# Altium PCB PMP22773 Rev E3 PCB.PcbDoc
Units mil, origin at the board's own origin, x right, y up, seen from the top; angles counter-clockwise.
Board outline 1255 x 1328.74 mil, 4 copper layers (Top Layer, GND, Signal, Bottom Layer), stack 70.356 mil thick; 34 components, 28 nets, 106 pads, 30 vias.
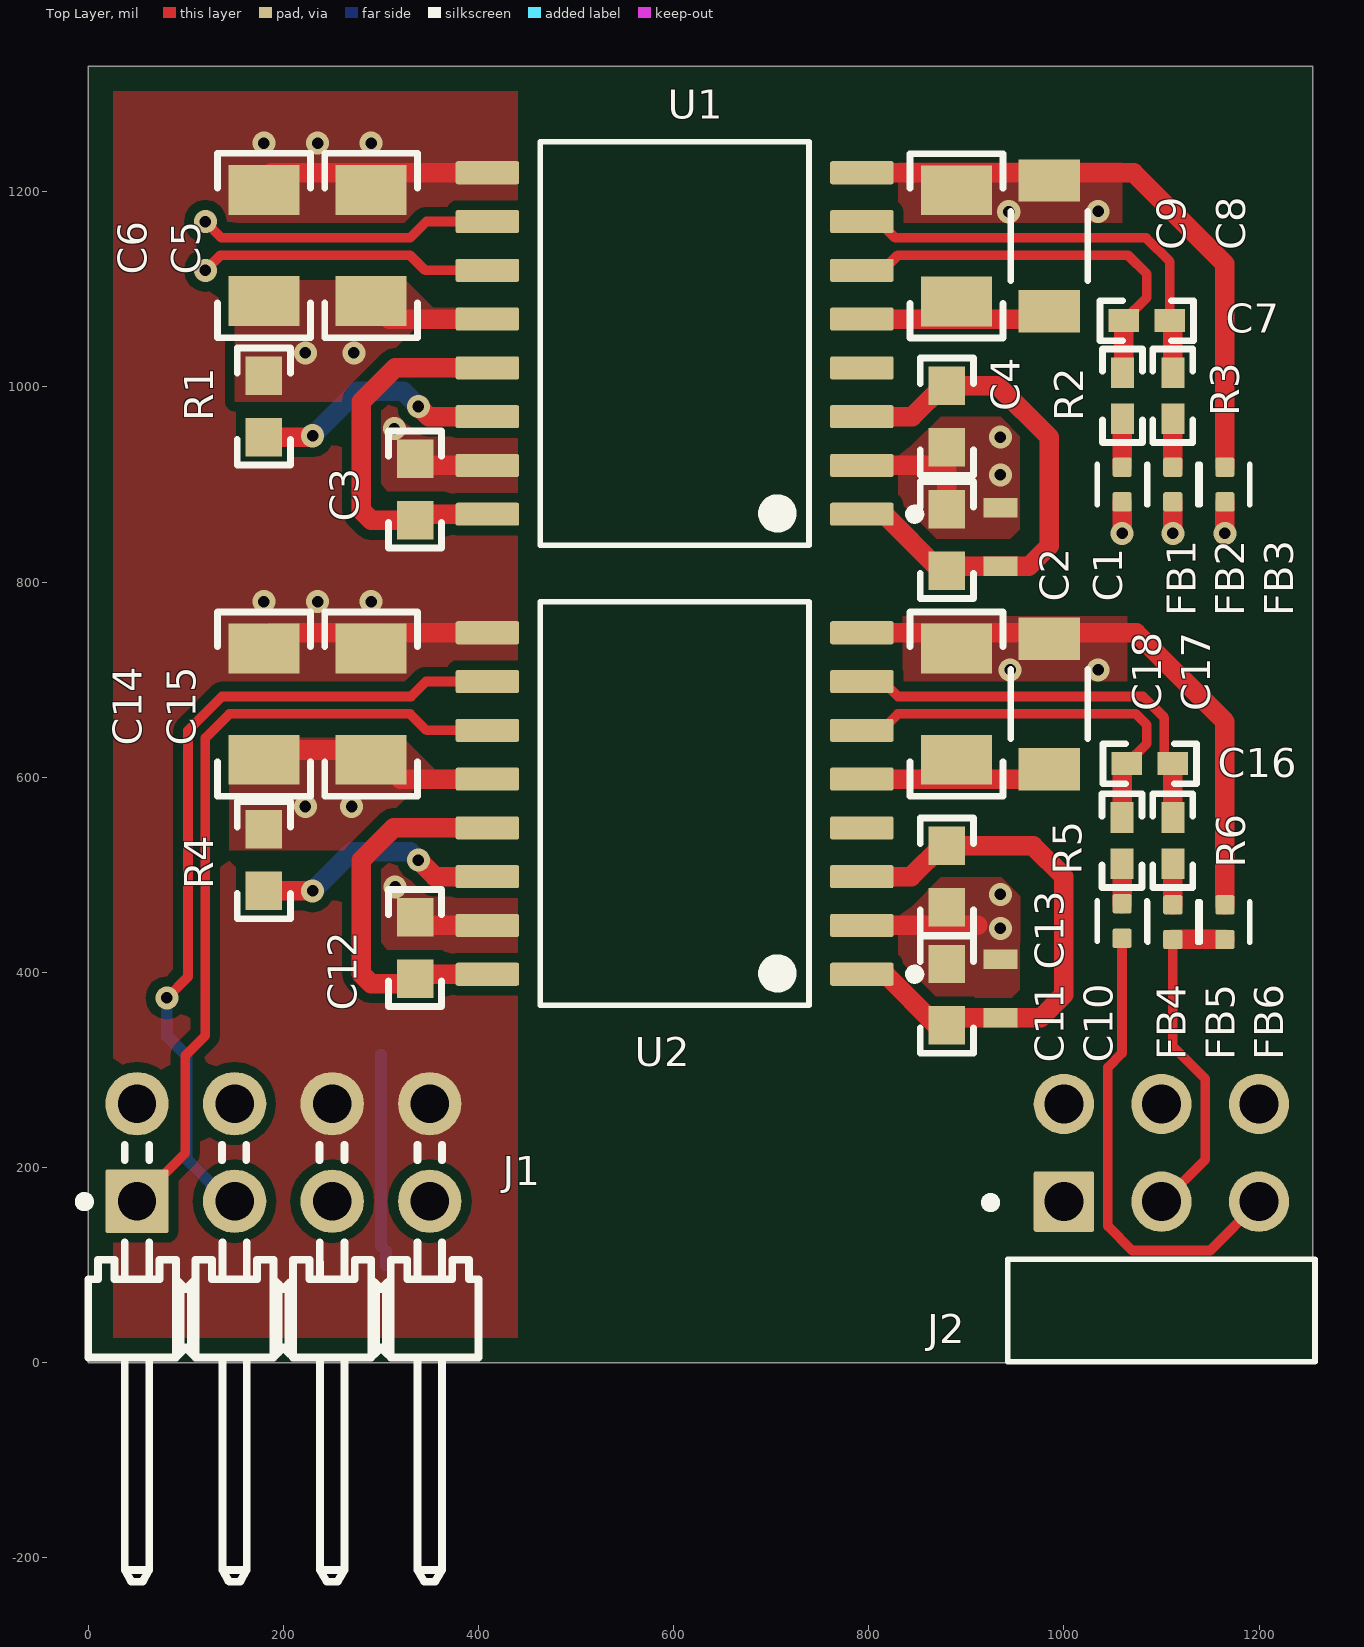
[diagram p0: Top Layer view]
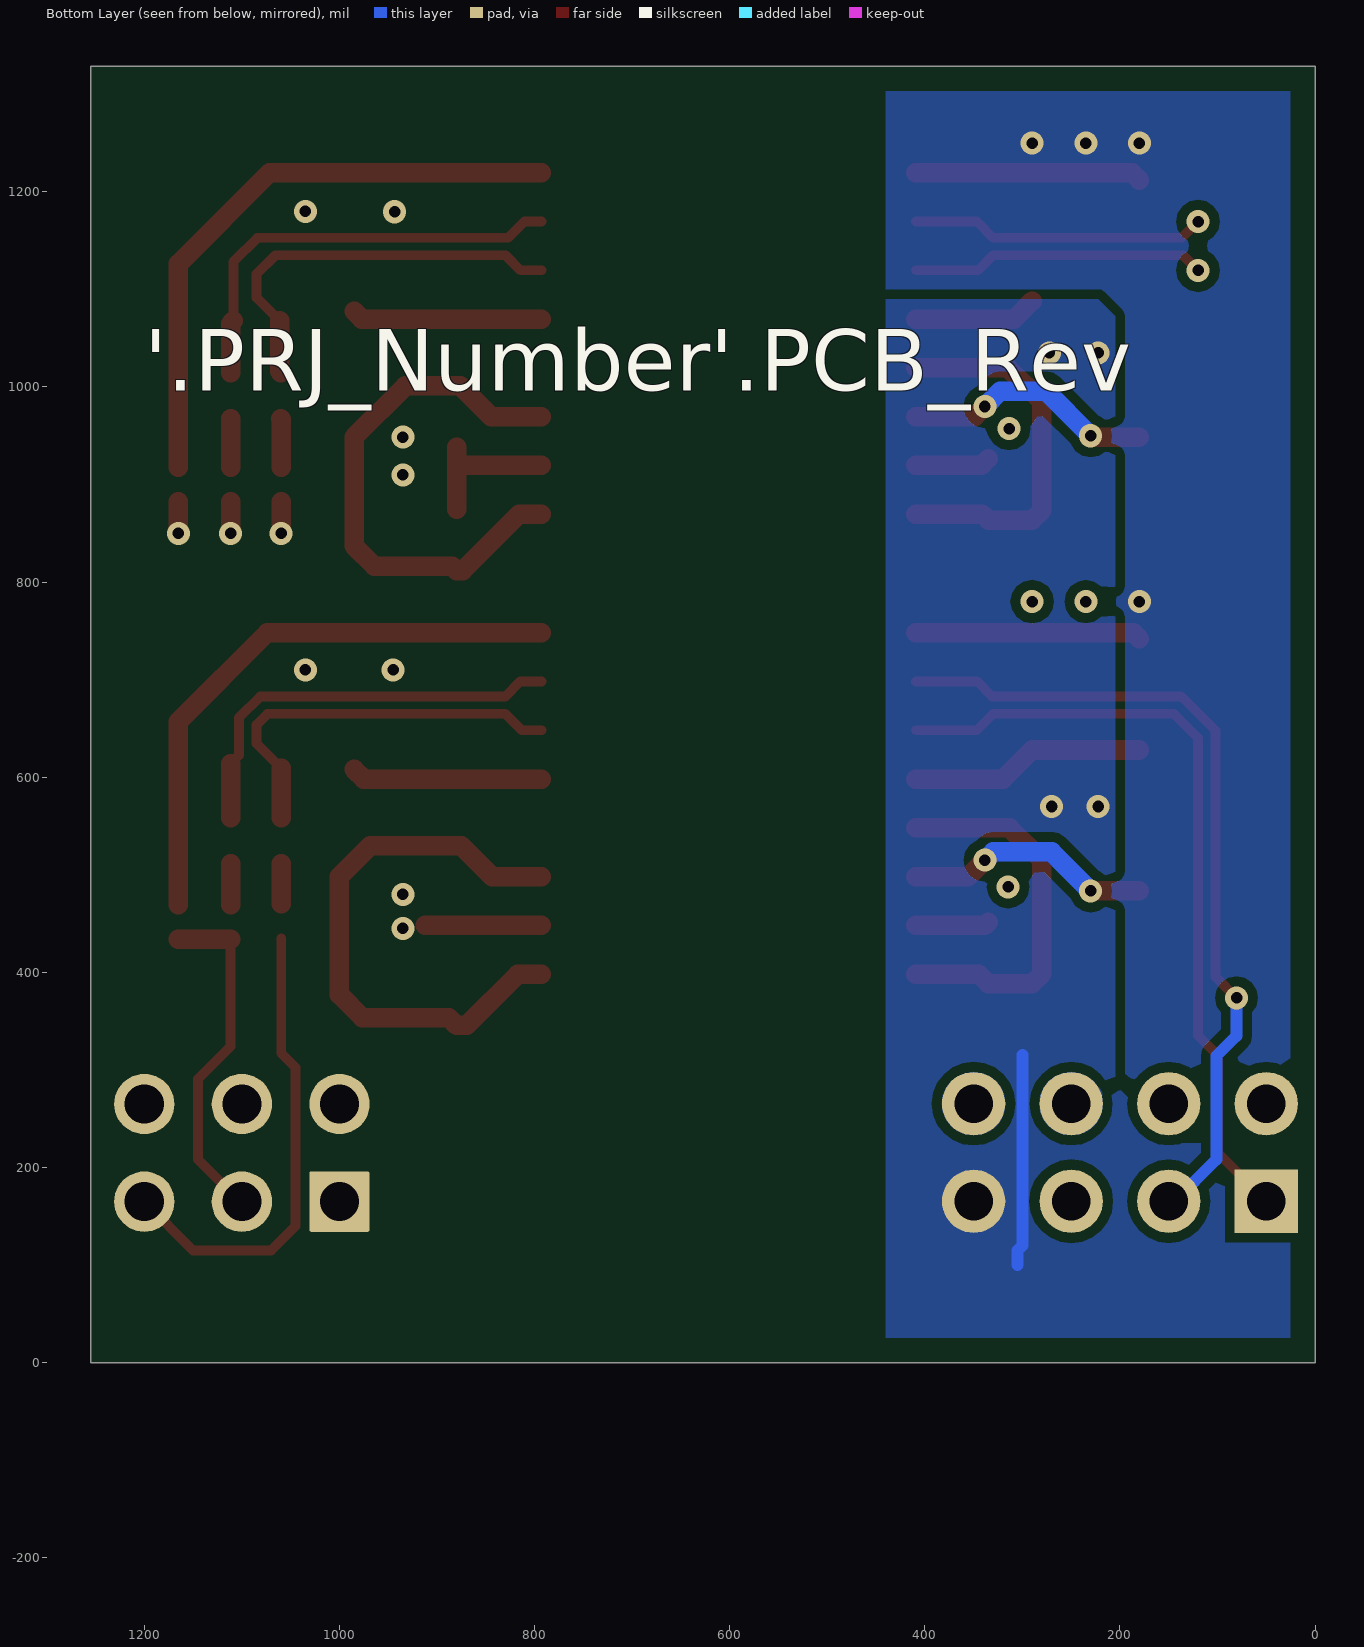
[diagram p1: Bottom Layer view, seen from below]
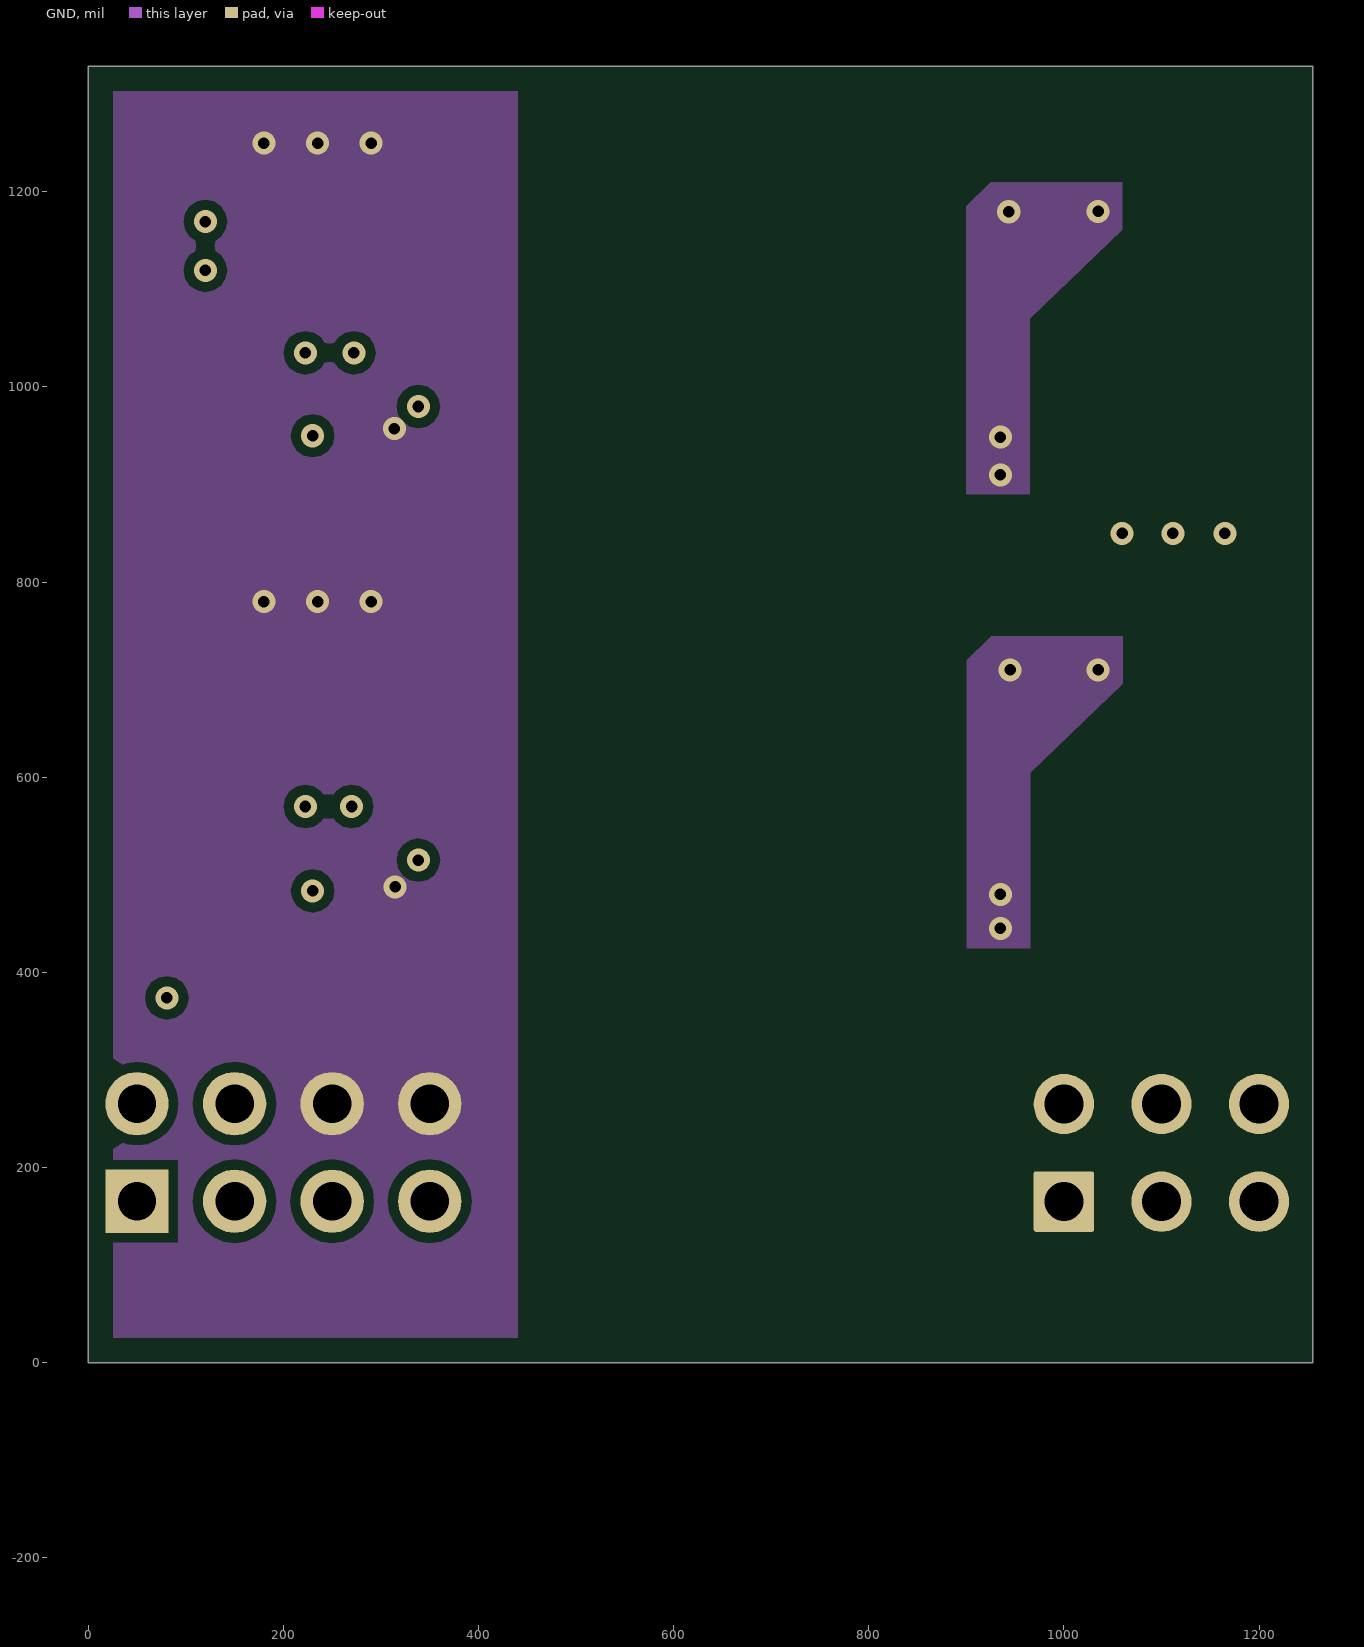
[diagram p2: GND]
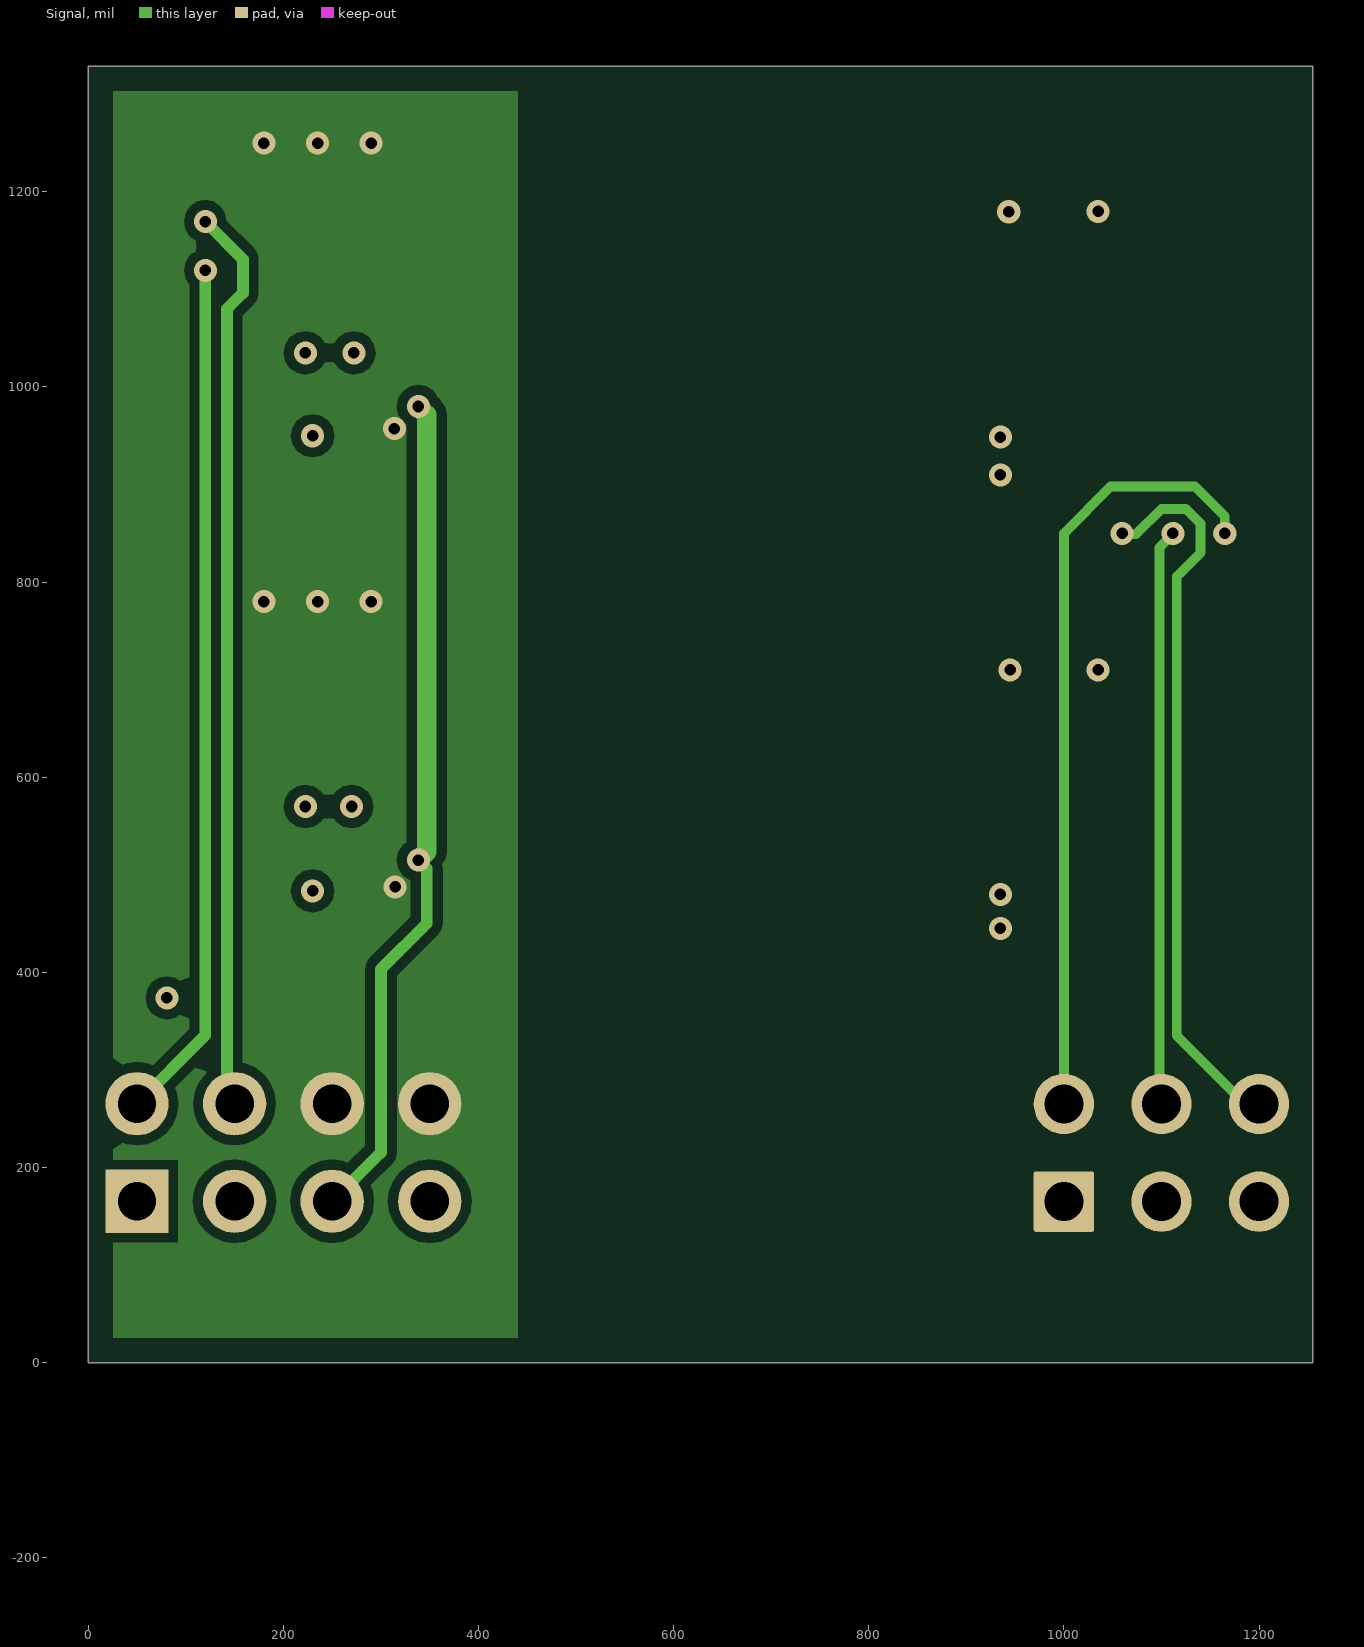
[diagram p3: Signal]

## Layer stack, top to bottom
Top Solder: solder mask 0.4, Solder Resist, Dk 3.5
Top Layer: signal copper 1.4
Dielectric 1: prepreg 2.8, PP-006, Dk 4.1
GND: signal copper 1.378
Dielectric1: core 59.2, FR-4, Dk 4.8
Signal: signal copper 1.378
Dielectric 2: prepreg 2.8, PP-006, Dk 4.1
Bottom Layer: signal copper 1.4
Bottom Solder: solder mask 0.4, Solder Resist, Dk 3.5

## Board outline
0,0 1255,0 1255,1328.74 0,1328.74

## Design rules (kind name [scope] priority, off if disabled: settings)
AcuteAngle [All] p1: minimum=4.50000000000000E+0001 checktracksonly=FALSE
AssemblyTestPointUsage [All] p1: valid=2
BoardOutlineClearance BoardOutlineClearance_MountingHoles [OnCopper and InComponentClass('Mounting Holes')] p1: gap=39.37 ignorepadtopadclearanceinfootprint=FALSE
BoardOutlineClearance BoardOutlineClearance_Poly [OnCopper and IsPoly] p2: gap=25 ignorepadtopadclearanceinfootprint=FALSE
BoardOutlineClearance [OnCopper and Not InComponentClass('Logo') and not InComponentClass('FiducialMark') and not InRegion(1000,500,4000,800) and not InPoly] p3: gap=75 ignorepadtopadclearanceinfootprint=FALSE
Clearance Clearance_Keepouts [((IsTrack Or IsArc) And Not InPoly) And IsFree and IsKeepOut vs ((IsTrack Or IsArc) And Not InPoly) And IsFree and IsKeepOut] p1: gap=0 ignorepadtopadclearanceinfootprint=FALSE
Clearance Clearance_Poly [InPolygon] p2: gap=10 ignorepadtopadclearanceinfootprint=TRUE
Clearance Clearance_FiducialMark [IsKeepOut and InComponentClass('FiducialMark') vs IsPad and InComponentClass('FiducialMark')] p3: gap=0 ignorepadtopadclearanceinfootprint=FALSE
Clearance [All] p4: gap=7.87 ignorepadtopadclearanceinfootprint=TRUE
ComponentClearance ComponentClearance_MountingHoles_FiducialMarks [InComponentClass('Mounting Holes') vs InComponentClass('FiducialMark')] p1: gap=50 collisioncheckmode=3 verticalgap=10 showdistances=FALSE
ComponentClearance ComponentClearance_Shunt [InComponentClass('Header') vs InComponentClass('Shunt')] p2: gap=0 collisioncheckmode=3 verticalgap=0 showdistances=FALSE
ComponentClearance ComponentClearance_Logo [InComponentClass('Logo')] p3: gap=50 collisioncheckmode=3 verticalgap=10 showdistances=FALSE
ComponentClearance ComponentClearance_ScrewToNut [(HasFootprint('NY PMS 440 0025 PH')) vs (HasFootprint('Keystone_1902C'))] p4: gap=5 collisioncheckmode=3 verticalgap=10 showdistances=FALSE
ComponentClearance ComponentClearance_MountingHoles [InComponentClass('Mounting Holes')] p5: gap=250 collisioncheckmode=3 verticalgap=100000 showdistances=FALSE
ComponentClearance ComponentClearance_SmallPassives [HasFootprint('0201*') or HasFootprint('0402*') or HasFootprint('0508') or HasFootprint('0603*') or HasFootprint('0612') or HasFootprint('0805*') or HasFootprint('0815*') or HasFootprint('0830*') or HasFootprint('1206*') or HasFootprint('1210*') or HasFootprint('1808*') or HasFootprint('1812*') or HasFootprint('1825*') or HasFootprint('2010*') or HasFootprint('2220*') or HasFootprint('2225*') or HasFootprint('2512*') or HasFootprint('2728*') or HasFootprint('3518*') vs HasFootprint('0201*') or HasFootprint('0402*') or HasFootprint('0508') or HasFootprint('0603*') or HasFootprint('0612') or HasFootprint('0805*') or HasFootprint('0815*') or HasFootprint('0830*') or HasFootprint('1206*') or HasFootprint('1210*') or HasFootprint('1808*') or HasFootprint('1812*') or HasFootprint('1825*') or HasFootprint('2010*') or HasFootprint('2220*') or HasFootprint('2225*') or HasFootprint('2512*') or HasFootprint('2728*') or HasFootprint('3518*')] p6: gap=14.96 collisioncheckmode=3 verticalgap=10 showdistances=FALSE
ComponentClearance ComponentClearance_THtoSMT [IsThruComponent vs IsSMTComponent] p7: gap=40 collisioncheckmode=3 verticalgap=30 showdistances=FALSE
ComponentClearance ComponentClearance_THtoTH [IsThruComponent vs IsThruComponent] p8: gap=30 collisioncheckmode=3 verticalgap=30 showdistances=FALSE
ComponentClearance [All] p9: gap=30 collisioncheckmode=3 verticalgap=10 showdistances=FALSE
DiffPairsRouting [All] p1: maxlimit=100 minlimit=10 mostfreqgap=10 toplayer_minwidth=15 toplayer_maxwidth=15 toplayer_prefwidth=15 midlayer1_minwidth=15 midlayer1_maxwidth=15 midlayer1_prefwidth=15 midlayer2_minwidth=15 midlayer2_maxwidth=15 midlayer2_prefwidth=15 bottomlayer_minwidth=15 bottomlayer_maxwidth=15 bottomlayer_prefwidth=15 maxuncoupledlength=1000
FabricationTestPointUsage TestPointUsage [All] p1: valid=2 allowmultiple=FALSE
FabricationTestpoint Testpoint [All] p1: side=3 testpointundercomponent=TRUE minsize=40 maxsize=100 preferedsize=60 minholesize=0 maxholesize=40 preferedholesize=32 testpointgrid=1 allowsidetop=TRUE allowsidebottom=TRUE usegrid=TRUE gridtolerance=0.01
FanoutControl Fanout_LCC [IsLCC] p1: bgadir=Out bgaviamode=Centered fanoutstyle=Auto fanoutdirection=Alternating viagrid=1 // Fanout_LCC (Default Rule)
FanoutControl Fanout_BGA [IsBGA] p2: bgadir=Out bgaviamode=Centered fanoutstyle=Auto fanoutdirection=Alternating viagrid=1 // Fanout_BGA (Default Rule)
FanoutControl Fanout_Default [All] p4: bgadir=Out bgaviamode=Centered fanoutstyle=Auto fanoutdirection=Alternating viagrid=1 // Fanout_Default (Default Rule)
FanoutControl Fanout_Small [(CompPinCount < 5)] p5: bgadir=Out bgaviamode=Centered fanoutstyle=Auto fanoutdirection=OutThenIn viagrid=1 // Fanout_Small (Default Rule)
HoleSize [All] p1: absolutevalues=TRUE maxlimit=251 minlimit=7.87 maxpercent=80.000 minpercent=20.000
MinimumAnnularRing MinimumAnnularRing_ThermalPadVias [IsVia and InAnyComponent] p1: minimumring=5.91
MinimumAnnularRing [All] p2: minimumring=7.87
MinimumSolderMaskSliver MinimumSolderMaskSliver_Logo [InComponentClass('Logo') vs InComponentClass('Logo')] p1: minsoldermaskwidth=0.7
MinimumSolderMaskSliver [All] p2: minsoldermaskwidth=3.94
PlaneConnect [All] p1: planeconnectstyle=Relief reliefexpansion=10 reliefentries=4 reliefconductorwidth=10 reliefairgap=10
PolygonConnect [All] p1: connectstyle=Direct reliefconductorwidth=10 reliefentries=4 polygonreliefangle="90 Angle" airgapwidth=10
RoutingVias ThermalPadVias [IsVia and InAnyComponent] p1: holewidth=7.87 width=19.68 viastyle="Through Hole" minholewidth=7.87 minwidth=19.68 maxholewidth=12.99 maxwidth=23.62
RoutingVias [All] p2: holewidth=16 width=34 viastyle="Through Hole" minholewidth=7.87 minwidth=26 maxholewidth=40 maxwidth=65
SilkToBoardRegionClearance [Not ((IsComment or IsDesignator) And (Hide <> 'False')) and not InRegion(1000,500,4000,800)] p1:
SilkToSilkClearance SilkToSilkClearance_Pb-FreeLogo [(HasFootprint('Pb-Free_Overlay_Medium') OR HasFootprint('Pb-Free_Overlay_Small')) vs (HasFootprint('Pb-Free_Overlay_Medium') OR HasFootprint('Pb-Free_Overlay_Small'))] p1: silktosilkclearance=0
SilkToSilkClearance [All] p2: silktosilkclearance=3.94
SilkToSolderMaskClearance SilkToComponentPadClearance [(IsPad or IsFill or IsRegion) and InAnycomponent] p1: minsilkscreentomaskgap=5 clearancetoexposedcopper=TRUE
SilkToSolderMaskClearance "Silk to Solder Mask Opening" [All] p2: minsilkscreentomaskgap=3.94 clearancetoexposedcopper=FALSE
SolderMaskExpansion [All] p1: expansion=1.97 istentingtop=FALSE
UnRoutedNet [All] p1: checkbadconnections=TRUE
Width [All] p1: maxlimit=100 minlimit=6 preferedwidth=10 checkconnectedcopper=TRUE
14 further rules are at their usual default settings.

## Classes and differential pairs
component class Header: J1

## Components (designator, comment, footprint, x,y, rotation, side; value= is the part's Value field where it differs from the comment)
C1 "CGA3E1X7R1E105K080AC" 0603S 935,846.22 r90 top value=1uF
C2 "C0603C102K5RACTU" 0603 880,843.11 r90 top value=1000pF
C3 "C0603C104K5RACAUTO" 0603 335,895 r90 top value=0.1uF
C4 "C0603C104K5RACAUTO" 0603 880,969.58 r90 top value=0.1uF
C5 "12065C102KAT2A" 1206 290,1145 r90 top value=1000pF
C6 "12063C105KAT2A" 1206 180,1145 r90 top value=1uF
C7 "CGA2B3X7R1H104K050BB" 0402 1085,1067.91 r180 top value=0.1uF
C8 "C3216NP01H104J160AA" 1206_190 985,1144.58 r90 top value=0.1uF
C9 "12065C102KAT2A" 1206 890,1144.58 r90 top value=1000pF
C10 "CGA3E1X7R1E105K080AC" 0603S 935,383.5 r90 top value=1uF
C11 "C0603C102K5RACTU" 0603 880,377.12 r90 top value=1000pF
C12 "C0603C104K5RACAUTO" 0603 335,425 r90 top value=0.1uF
C13 "C0603C104K5RACAUTO" 0603 880,498.09 r90 top value=0.1uF
C14 "12065C102KAT2A" 1206 180,675 r90 top value=1000pF
C15 "12063C105KAT2A" 1206 290,675 r90 top value=1uF
C16 "CGA2B2X7R1H102K050BA" 0402 1088.03,613.86 r180 top value=1000pF
C17 "C3216NP01H104J160AA" 1206_190 985,675 r90 top value=0.1uF
C18 "12065C102KAT2A" 1206 890,675 r90 top value=1000pF
FB1 "MMZ1005Y182CTD25" FP-MMZ1005Y182CTD25_0402-MFG 1059.69,900 r90 top
FB2 "MMZ1005Y182CTD25" FP-MMZ1005Y182CTD25_0402-MFG 1111.65,900 r90 top
FB3 "MMZ1005Y182CTD25" FP-MMZ1005Y182CTD25_0402-MFG 1165,900 r90 top
FB4 "MMZ1005Y182CTD25" FP-MMZ1005Y182CTD25_0402-MFG 1059.69,452.6 r90 top
FB5 "MMZ1005Y182CTD25" FP-MMZ1005Y182CTD25_0402-MFG 1111.65,451.5 r90 top
FB6 "MMZ1005Y182CTD25" FP-MMZ1005Y182CTD25_0402-MFG 1165,451.5 r90 top
J1 "TSW-104-09-G-D-RA" Samtec_TSW-104-09-G-D-RA 200,215.39 r0 top
J2 "TSW-103-08-G-D-RA" FP-TSW-103-08-G-D-RA_HDR6-MFG 1100,55.94 r0 top
R1 "CRCW060347K0JNEA" 0603 180,980 r270 top value=47k
R2 "CRCW040239R2FKED" 0402 1060,991.08 r90 top value=39.2
R3 "CRCW040239R2FKED" 0402 1111.65,991.08 r90 top value=39.2
R4 "CRCW060347K0JNEA" 0603 180,515 r270 top value=47k
R5 "CRCW04020000Z0ED" 0402 1059.69,535 r90 top value=0
R6 "CRCW04020000Z0ED" 0402 1111.65,535 r90 top value=0
U1 "PAMC3302DWER" DWE0016A-MFG 601,1044.58 r180 top
U2 "AMC3330QDWERQ1" DWE0016A-MFG 601,573.09 r180 top

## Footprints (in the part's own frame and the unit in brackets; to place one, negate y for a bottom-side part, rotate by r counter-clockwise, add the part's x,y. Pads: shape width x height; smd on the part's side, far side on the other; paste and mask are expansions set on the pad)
0402 [mm] "0402 from SM-752 data"
  rect 0.8x0.6 smd: 1(-0.6,0) 2(0.6,0)
  silkscreen extent -1.22,-0.52 1.22,0.52, body extent -0.55,-0.3 0.55,0.3, height 0.6
0603 [mm] "0603 from SM-752 data"
  rect 1x0.95 smd: 1(-0.8,0) 2(0.8,0)
  silkscreen extent -1.52,-0.69 1.52,0.69, body extent -0.87,-0.47 0.87,0.47, height 1
0603S [mil]
  rect 20x35 smd: 1(-30,0) 2(30,0)
  body extent -34,-19 34,19, height 39
1206 [mm] "1206 from SM-752 data"
  rect 1.3x1.85 smd: 1(-1.45,0) 2(1.45,0)
  silkscreen extent -2.4,-1.21 2.4,1.21, body extent -1.7,-0.9 1.7,0.9, height 1.35
1206_190 [mm] "1206_190"
  rect 1.1x1.6 smd: 1(-1.7,0) 2(1.7,0)
  silkscreen extent -0.9,-1 0.9,1, body extent -1.75,-0.95 1.75,0.95, height 1.9
DWE0016A-MFG [mm]
  rrect17% 1.65x0.6 smd paste+0 mask+0: 1(-4.875,4.445) 2(-4.875,3.175) 3(-4.875,1.905) 4(-4.875,0.635) 5(-4.875,-0.635) 6(-4.875,-1.905) 7(-4.875,-3.175) 8(-4.875,-4.445) 9(4.875,-4.445) 10(4.875,-3.175) 11(4.875,-1.905) 12(4.875,-0.635) 13(4.875,0.635) 14(4.875,1.905) 15(4.875,3.175) 16(4.875,4.445)
  silkscreen extent -6.38,-5.25 3.5,5.25, body extent -5.8,-5.5 5.8,5.5, height 0.25
FP-MMZ1005Y182CTD25_0402-MFG [mm]
  rrect20% 0.5x0.5 smd paste+0 mask+0: 1(-0.45,0) 2(0.45,0)
  silkscreen extent -0.53,-0.65 0.53,0.65, body extent -0.8,-0.38 0.8,0.38, height 0.25
FP-TSW-103-08-G-D-RA_HDR6-MFG [mm]
  rrect6% 1.57x1.57 hole 1.02 paste-1000 mask+0: 1(-2.54,2.77)
  round 1.57 hole 1.02 paste-1000 mask+0: 2(-2.54,5.31) 3(0,2.77) 4(0,5.31) 5(2.54,2.77) 6(2.54,5.31)
  silkscreen extent -4.57,-1.4 4,2.87, body extent -4.1,-7.54 4.1,6.19, height 0.25
Samtec_TSW-104-09-G-D-RA [mm] "Samtec Right Angle Header"
  rrect6% 1.65x1.65 / inner rect 1.65x1.65 / far side rect 1.65x1.65 hole 1: 1(-3.81,-1.27)
  round 1.65 hole 1: 2(-3.81,1.27) 3(-1.27,-1.27) 4(-1.27,1.27) 5(1.27,-1.27) 6(1.27,1.27) 7(3.81,-1.27) 8(3.81,1.27)
  silkscreen extent -5.3,-11.18 5.08,0.2, body extent -5.08,-11.18 5.08,1.59, height 5.51

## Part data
C1 C10: library part CMP-0076705-3, "CAP, CERM, 1 µF, 25 V,+/- 10%, X7R, AEC-Q200 Grade 1, 0603", Cap_Case=1.6x0.8x0.8mm, Manufacturer=TDK, Supplier Part Number 1=445-6931-1-ND, TempCo=X7R, Tolerance_%=10%, Value2=25V, ValueDisplayed=1µF
C2 C11: library part CMP-0006847-4, "CAP, CERM, 1000 pF, 50 V, +/- 10%, X7R, 0603", Cap_Case=0603, Manufacturer=Kemet, Supplier Part Number 1=399-1082-1-ND, TempCo=X7R, Tolerance_%=10%, Value1=Unknown, Value2=50V, ValueDisplayed=1000pF
C3 C4 C12 C13: library part CMP-0079602-1, "CAP, CERM, 0.1 µF, 50 V,+/- 10%, X7R, AEC-Q200 Grade 1, 0603", Cap_Case=0603, Manufacturer=Kemet, Supplier Part Number 1=399-6856-1-ND, TempCo=X7R, Tolerance_%=10%, Value2=50V, ValueDisplayed=0.1µF
C5 C9 C14 C18: library part CMP-0008530-2, "CAP, CERM, 1000 pF, 50 V, +/- 10%, X7R, 1206", Cap_Case=1206, Manufacturer=AVX, Supplier Part Number 1=478-1530-1-ND, TempCo=X7R, Tolerance_%=10%, Value1="0.427 ohm", Value2=50V, ValueDisplayed=1000pF
C6 C15: library part CMP-0008509-2, "CAP, CERM, 1 uF, 25 V, +/- 10%, X7R, 1206", Cap_Case=1206, Manufacturer=AVX, Supplier Part Number 1=478-1567-1-ND, TempCo=X7R, Tolerance_%=10%, Value1="0.013 ohm", Value2=25V, ValueDisplayed=1uF
C7: library part CMP-0006325-2, "CAP, CERM, 0.1 uF, 50 V, +/- 10%, X7R, AEC-Q200 Grade 1, 0402", Cap_Case=0402, Manufacturer=TDK, Supplier Part Number 1=445-6899-1-ND, TempCo=X7R, Tolerance_%=10%, Value1="0.039064 ohm", Value2=50V, ValueDisplayed=0.1uF
C8 C17: library part CMP-0008647-2, "CAP, CERM, 0.1 uF, 50 V, +/- 5%, C0G/NP0, 1206_190", Cap_Case=1206, Manufacturer=TDK, Supplier Part Number 1=445-14655-1-ND, TempCo=C0G/NP0, Tolerance_%=5%, Value1=Unknown, Value2=50V, ValueDisplayed=0.1uF
C16: library part CMP-0006314-2, "CAP, CERM, 1000 pF, 50 V, +/- 10%, X7R, AEC-Q200 Grade 1, 0402", Cap_Case=0402, Manufacturer=TDK, Supplier Part Number 1=445-5605-1-ND, TempCo=X7R, Tolerance_%=10%, Value1="2.25564 ohm", Value2=50V, ValueDisplayed=1000pF
FB1 FB2 FB3 FB4 FB5 FB6: library part CMP-0090600-1, "1.8 kOhms @ 100MHz 1 Signal Line Ferrite Bead 0402 (1005 Metric) 150mA 850mOhm", Digikey Part Number=445-172716-1-ND, Impedance At Frequency="1800Ω @ 100MHz", Manufacturer=TDK, Mouser Part Number=810-MMZ1005Y182CTD25, Operating Temperature Range="-55°C to +125°C", Test Frequency=100MHz, Tolerance_%=25%
J1: library part CMP-0075584-2, "Header, 100mil, 4x2, Gold, R/A, TH", Color=Black, Current_A=6.3A, Manufacturer=Samtec, Supplier Part Number 1=79P5069, Voltage_V=550V
J2: library part CMP-0090622-1, "Connector Header Through Hole, Right Angle 6 position 0.100\" (2.54mm)", Current_A=5.7A, Digikey Part Number=SAM1037-03-ND, Manufacturer=Samtec, Mouser Part Number=200-TSW10308GDRA, Operating Temperature Range="-55°C to +125°C", Voltage_V=550V
R1 R4: library part CMP-0025814-4, "RES, 47 k, 5%, 0.1 W, AEC-Q200 Grade 0, 0603", Manufacturer=Vishay-Dale, Power_W=100mW, Supplier Part Number 1=541-47KGCT-ND, TempCo="200 ppm/C", Tolerance_%=5%, Value2=0.1W, Value_Code=47k0, ValueDisplayed=47k
R2 R3: library part CMP-0026328-2, "RES, 39.2, 1%, 0.063 W, AEC-Q200 Grade 0, 0402", Manufacturer=Vishay-Dale, Power_W=63mW, Supplier Part Number 1=541-39.2LCT-ND, TempCo="100 ppm/C", Tolerance_%=1%, Value2=0.063W, Value_Code=39R2, ValueDisplayed=39.2
R5 R6: library part CMP-0026822-3, "RES, 0, 5%, 0.063 W, AEC-Q200 Grade 0, 0402", Manufacturer=Vishay-Dale, Power_W=63mW, Supplier Part Number 1=541-0.0JCT-ND, TempCo="200 ppm/C", Tolerance_%=5%, Value2=0.063W, Value_Code=0000, ValueDisplayed=0
U1: library part CMP-0090884-2, "±50-mV input, precision reinforced isolated amplifier with integrated DC/DC converter 16-SOIC -40 to 125", Input Bias Current=-36uA, Input Offset Voltage=0.1mV, Manufacturer="Texas Instruments", Max Supply Voltage=5.5V, Min Supply Voltage=3V, Nominal Supply Current=27.5-29.5mA, Operating Temperature Range="-40°C to +125°C", Output Current Per Channel=14mA
U2: library part CMP-0090627-1, "Precision, ±1-V Input, Reinforced Isolated Amplifier With Integrated DC/DC Converter", Input Bias Current=0.01uA, Manufacturer="Texas Instruments", Max Supply Voltage=5.5V, Min Supply Voltage=3V, Nominal Supply Current=27.5-28.5mA, Operating Temperature Range="-40°C to +125°C"

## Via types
v1: diameter 23.62, hole 11.81, Top Layer to Bottom Layer, 30 vias

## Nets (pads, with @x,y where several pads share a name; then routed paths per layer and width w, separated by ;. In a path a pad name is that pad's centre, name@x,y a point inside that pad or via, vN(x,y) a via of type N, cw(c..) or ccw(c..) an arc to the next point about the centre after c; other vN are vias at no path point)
3V3_PRI: C5.1 C6.1 C14.1 C15.1 J1.7 R1.1 R4.1 U1.12 U2.12 | length 585.8
  Top Layer w20: C14.1@180,627.91 290,627.91 319.82,598.09 U2.12 ; C5.1 308.33,1069.58 U1.12
  Bottom Layer w12: 300,315.6 300,120 305,115 305,100
  other v1: 222.5,570 270,570 222.5,1035 272.25,1035
BATT_RTN: FB1.1 J2.6 | length 749.1
  Top Layer w20: FB1.1 1059.69,849.4 v1@1060,849.08
  Signal w10: v1@1060,849.08 1074.08,849.08 1100,875 1125,875 1140,860 1140,830 1115.75,805.75 1115.75,335 J2.6@1175,275.75
  other v1: 1059.69,850
CLLLC_SEC_SIDE_SENSE_DIAG: J1.5 R1.2 R4.2 U1.14 U2.14 | length 1381
  Top Layer w20: R4.2 v1(230,483.5) ; R1.2 228.5,948.5 v1(230,950) ; v1(338.41,515) 355.32,498.09 U2.14 ; v1(338.41,980) 348.83,969.58 U1.14
  Signal w12: J1.5 300,215.39 300,403.19 346.92,450.1 346.92,506.49 v1(338.41,515)
  Signal w20: v1(338.41,515) 346.92,523.51 346.92,971.49 v1(338.41,980)
  Bottom Layer w20: v1(230,483.5) 270.01,523.51 329.9,523.51 v1(338.41,515) ; v1(230,950) 275.72,995.72 322.68,995.72 v1(338.41,980)
GND_SNS1: FB2.1 J2.4 | length 623.9
  Top Layer w20: v1@1111.65,849.08 FB2.1
  Signal w10: J2.4 1097.87,267.13 1097.87,835.31 v1@1111.65,849.08
  other v1: 1111.65,850
GND_SNS2: FB3.1 J2.2 | length 834.2
  Top Layer w20: v1(1165,850) FB3.1
  Signal w10: J2.2 1000,850 1047.87,897.87 1134.47,897.87 1165,867.35 v1(1165,850)
  Signal w20: v1@1162.87,850 v1(1165,850)
ISNS_OUTN: J1.4 U1.10 | length 1233
  Top Layer w10: v1(120,1169.58) 136.71,1152.87 330,1152.87 346.71,1169.58 U1.10
  Signal w12: v1(120,1169.58) 158.55,1131.03 158.55,1096.31 142.24,1080 142.24,273.16 J1.4
ISNS_OUTP: J1.2 U1.11 | length 1185
  Top Layer w10: v1(120,1119.58) 135.42,1135 330,1135 345.42,1119.58 U1.11
  Signal w12: J1.2 120,335.39 v1(120,1119.58)
NetC1_1: C1.1 C2.1 C4.2 U1.1 U1.3 | length 565
  Top Layer w20: U1.1 815.7,869.58 873.66,811.62 C2.1 884.61,816.22 C1.1 964.18,816.22 985,837.05 985,948.5 932.43,1001.08 C4.2 876.08,1001.08 844.58,969.58 U1.3
NetC1_2: C1.2 C2.2 C4.1 C8.2 C9.2 FB3.2 U1.2 U1.8 | length 769.7
  Top Layer w20: U1.2 C4.1@880,919.58 ; U1.8 1071.51,1219.58 1165,1126.09 FB3.2 ; C2.2 C4.1
  other v1: 935,910 935,948.5 943.5,1179.58 1035,1180
NetC3_1: C3.1 U1.13 U1.16 | length 390.6
  Top Layer w20: U1.16 341.08,869.58 C3.1 290,863.5 280,873.5 280,985 314.58,1019.58 U1.13
NetC7_1: C7.1 R3.2 U1.7 | length 447.7
  Top Layer w10: U1.7 810.45,1169.58 827.15,1152.87 1084.16,1152.87 1108.62,1128.41 C7.1
  Top Layer w20: C7.1 1111.65,1064.88 R3.2
NetC7_2: C7.2 R2.2 U1.6 | length 417.8
  Top Layer w10: U1.6 814.28,1119.58 829.7,1135 1065.67,1135 1085,1115.67 1085,1091.54 C7.2
  Top Layer w20: R2.2 1061.38,1016.08 C7.2
NetC8_1: C8.1 C9.1 U1.5 | length 195.4
  Top Layer w20: U1.5 976.93,1069.58 C8.1
NetC10_1: C10.1 C11.1 C13.2 U2.1 U2.3 | length 596
  Top Layer w20: U2.1 817.19,398.09 869.65,345.62 C11.1 887.88,353.5 C10.1 976.39,353.5 1000,377.12 1000,498.09 968.5,529.59 C13.2 874.92,529.59 843.43,498.09 U2.3
NetC10_2: C10.2 C11.2 C13.1 C17.2 C18.2 FB6.2 U2.2 U2.8 | length 716.6
  Top Layer w20: U2.2 911.91,448.09 ; U2.8 1074,748.09 1165,657.09 FB6.2
  other v1: 935,445 935,480 945,710 1035,710
NetC12_1: C12.1 U2.13 U2.16 | length 396.5
  Top Layer w20: U2.16 344.59,398.09 335,388.5 290,388.5 280,398.5 280,515 313.09,548.09 U2.13
NetC16_1: C16.1 R6.2 U2.7 | length 431.4
  Top Layer w10: U2.7 814.78,698.09 830,682.87 1081.09,682.87 1102.87,661.09 1102.87,622.64 C16.1
  Top Layer w20: R6.2 C16.1
NetC16_2: C16.2 R5.2 U2.6 | length 409.3
  Top Layer w10: U2.6 813.09,648.09 830,665 1073.69,665 1085,653.69 1085,634.45 C16.2 C16.2@1059.69,609.14
  Top Layer w20: R5.2 C16.2@1059.69,609.14
NetC17_1: C17.1 C18.1 U2.5 | length 196.2
  Top Layer w20: U2.5 975.02,598.09 C17.1
NetFB1_2: FB1.2 R2.1 | length 49.9
  Top Layer w20: FB1.2 1059.69,967.14 R2.1
NetFB2_2: FB2.2 R3.1 | length 49.7
  Top Layer w20: FB2.2 R3.1
NetFB4_2: FB4.2 R5.1 | length 41.1
  Top Layer w20: FB4.2 R5.1
NetFB5_2: FB5.2 R6.1 | length 42.2
  Top Layer w20: FB5.2 R6.1
PGND: C3.2 C5.2 C6.2 C12.2 C14.2 C15.2 J1.6 J1.8 U1.9 U1.15 U2.9 U2.15 | length 616.1
  Top Layer w20: C14.2@180,742.09 186,748.09 290,748.09 U2.9 ; C6.2@180,1212.09 187.49,1219.58 290,1219.58 U1.9 ; C12.2@335,451.5 338.41,448.09 U2.15 ; C3.2 341.92,919.58 U1.15
  other v1: 314.58,487.62 180,780 235,780 290,780 313.72,957.23 180,1250 235,1250 290,1250
VSNS_INN: FB5.1 FB6.1 J2.3 | length 355.6
  Top Layer w10: J2.3 1101.76,165 1145,208.24 1145,290.69 1111.65,324.04 FB5.1
  Top Layer w20: FB5.1 FB6.1
VSNS_INP: FB4.1 J2.5 | length 487
  Top Layer w10: FB4.1 1059.69,317.14 1045,302.45 1045,140 1070,115 1150,115 J2.5
VSNS_OUTN: J1.3 U2.10 | length 851.5
  Top Layer w10: v1(80.53,373.9) 102.13,395.49 102.13,647.84 137.16,682.87 330.96,682.87 346.18,698.09 U2.10
  Bottom Layer w12: v1(80.53,373.9) 80.53,334.86 101.08,314.32 101.08,208.24 143.92,165.39 J1.3
VSNS_OUTP: J1.1 U2.11 | length 810.3
  Top Layer w10: J1.1 99.45,214.85 99.45,314.85 120,335.39 120,382.17 120,640.43 144.57,665 330,665 346.91,648.09 U2.11
pads on no net: J2.1 U1.4 U2.4

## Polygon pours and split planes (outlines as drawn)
NetC10_2 on GND "GND_NETC10_2_P017" (solid, remove dead copper, pour order 17): 965.47,424.7 965.47,604.7 1060.47,695.77 1060.47,744.7 925.47,744.7 900.47,719.7 900.47,644.7 900.47,424.7
NetC1_2 on GND "GND_NETC1_2_P014" (solid, remove dead copper, pour order 14): 965,890 965,1070 1060,1161.07 1060,1210 925,1210 900,1185 900,1110 900,890
PGND on GND "GND_PGND_P000" (solid, remove dead copper, pour order 0): 5,1325 440,1325 440,5 5,5
NetC10_2 on Top Layer "TOP_LAYER_NETC10_2_P016" (solid, remove dead copper, pour order 16): 835,765 835,696.07 1065,696.07 1065,765
NetC10_2 on Top Layer "TOP_LAYER_NETC10_2_P015" (solid, remove dead copper, pour order 15): 830.16,457.28 844.32,467.91 873.82,497.41 935.58,497.41 955.16,477.83 954.84,382.17 945.16,372.49 864.81,372.49 830.16,402.43
NetC1_2 on Top Layer "TOP_LAYER_NETC1_2_P013" (solid, remove dead copper, pour order 13): 830,929.45 844.17,940.09 873.66,969.58 935.42,969.58 955,950 954.68,854.35 945,844.66 864.66,844.66 830,874.61
NetC1_2 on Top Layer "TOP_LAYER_NETC1_2_P012" (solid, remove dead copper, pour order 12): 830,1230 830,1161.07 1060,1161.07 1060,1230
PGND on Top Layer "TOP_LAYER_PGND_P005" (solid, remove dead copper, pour order 5): 5,1325 440,1325 440,5 5,5
3V3_PRI on Top Layer "TOP_LAYER_3V3_PRI_P004" (solid, remove dead copper, pour order 4): 150,985 260,985 335,1060 385,1060 385,1081.25 353.44,1081.25 325.43,1109.26 150,1109.26
PGND on Top Layer "TOP_LAYER_PGND_P003" (solid, remove dead copper, pour order 3): 144.57,1180 120,1204.57 120,1276.51 144.57,1301.08 440,1301.08 440,1212.09 437.91,1210 355.51,1210 325.51,1180
3V3_PRI on Top Layer "TOP_LAYER_3V3_PRI_P001" (solid, remove dead copper, pour order 1): 144.57,640.43 325.43,640.43 325.43,637.95 355.32,608.07 272.25,525 144.57,525
PGND on Bottom Layer "BOTTOM_LAYER_PGND_P007" (solid, remove dead copper, pour order 7): 5,1325 440,1325 440,5 5,5
3V3_PRI on Bottom Layer "BOTTOM_LAYER_3V3_PRI_P002" (solid, remove dead copper, pour order 2): 5,225 145,225 205,285 205,1072.5 222.5,1090 440,1090 440,5 5,5
PGND on Signal "SIGNAL_PGND_P006" (solid, remove dead copper, pour order 6): 5,1325 440,1325 440,5 5,5

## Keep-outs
Keep-Out Layer:
  text ".Layer_Name" at 577,-858.49 h30

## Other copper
Top Layer:
  text ".Layer_Name" at 577,-858.49 h30
Bottom Layer:
  text ".Layer_Name" at 577,-858.49 h30

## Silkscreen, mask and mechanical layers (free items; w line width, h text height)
Top Overlay:
  text ".Layer_Name" at 577,-858.49 h30
Bottom Overlay:
  text "'.PRJ_Number'.PCB_Rev" at 1200,975 h108.27
  text ".Layer_Name" at 577,-858.49 h30
Top Paste:
  text ".Layer_Name" at 577,-858.49 h30
Bottom Paste:
  text ".Layer_Name" at 577,-858.49 h30
Top Solder:
  text ".Layer_Name" at 577,-858.49 h30
  text ".Layer_Name" at 577,-858.49 h30
Bottom Solder:
  text ".Layer_Name" at 577,-858.49 h30
Drill Guide:
  text ".Layer_Name" at 577,-858.49 h30
M1 Board Outline:
  the board outline again, w10
  text ".Layer_Name" at 577,-858.49 h30
M2 Board Dimensions:
  rectangle: 0,-275 125,-150
  rectangle: 125,-400 500,-275
  lines w7: 0,-275 1000,-275 ; 125,-400 125,-150 ; 250,-400 250,-150 ; 500,-400 500,-150 ; 750,-400 750,-150 ; 0,-400 1000,-400 1000,-150 0,-150 0,-400
  text ".Layer_Name" at 577,-858.49 h30
M3 3D STEP Top:
  text ".Layer_Name" at 577,-858.49 h30
M4 3D STEP Bottom:
  text ".Layer_Name" at 577,-858.49 h30
M5 Assembly Top:
  lines w10: -292,-930.17 6308,-930.17 ; -292,-726.83 6310,-726.83 ; -292,-523.5 -292,-1133.5 3713,-1133.5 6310,-1133.5 6310,-523.5 -291.5,-523.5 -291.5,-1133.5 1284,-1133.5 ; 2173,-1133.5 2173,-523.5 ; 3440,-726.83 3440,-523.5 ; 4280,-726.83 4280,-523.5 ; 4902,-1140 4902,-937.17
  text "COMPONENTS MARKED 'DNP' SHOULD NOT BE POPULATED." at 1153.5,-318.5 h30
  text "ASSEMBLY VARIANT:" at 1153,-434 h30
  text ".VariantName" at 2189,-434 h30
  text "PCB VIEWED FROM TOP SIDE" at -228.5,-655.67 h30
  text "BOARD #:" at 2248,-655.67 h30
  text ".PRJ_Number" at 2793.5,-655.67 h30
  text "REV:" at 3638,-655.67 h30
  text ".PCB_Rev" at 3929.5,-655.67 h30
  text "SVN REV:" at 4476,-655.67 h30
  text ".VersionControl_RevNumber" at 4982,-655.67 h30
  text "TID #:" at 2248,-859 h30
  text ".TID" at 2793.5,-859 h30
  text "PLOT NAME =" at -228.5,-1064.34 h30
  text ".plot_File_Name" at 577,-1064.34 h30
  text "GENERATED    :" at 2250,-1064.34 h30
  text ".Print_Date" at 3119.5,-1064.34 h30
  text ".Print_Time" at 3848.5,-1064.34 h30
  text "TEXAS INSTRUMENTS" at 5113,-1064.34 h30
M6 Assembly Bottom:
  lines w10: -292.5,-727.33 6309.5,-727.33 ; -290.5,-930.67 6309.5,-930.67 ; 1115.5,-1140.5 1115.5,-937.67 ; 1737.5,-727.33 1737.5,-524 ; 2577.5,-727.33 2577.5,-524 ; 3844.5,-1134 3844.5,-524 ; 4733.5,-1134 6309,-1134 6309,-524 -292.5,-524 -292.5,-1134 2304.5,-1134 6309.5,-1134 6309.5,-524
  text "COMPONENTS MARKED 'DNP' SHOULD NOT BE POPULATED." at 6102,-318 h30
  text ".VariantName" at 5058,-434 h30
  text "ASSEMBLY VARIANT:" at 6097,-434 h30
  text ".VersionControl_RevNumber" at 1035.5,-656.17 h30
  text "SVN REV:" at 1541.5,-656.17 h30
  text ".PCB_Rev" at 2088,-656.17 h30
  text "REV:" at 2379.5,-656.17 h30
  text ".PRJ_Number" at 3224,-656.17 h30
  text "BOARD #:" at 3769.5,-656.17 h30
  text "PCB VIEWED FROM BOTTOM SIDE" at 6246,-656.17 h30
  text ".TID" at 3224,-859.5 h30
  text "TID #:" at 3769.5,-859.5 h30
  text "TEXAS INSTRUMENTS" at 904.5,-1064.84 h30
  text ".Print_Time" at 2169,-1064.84 h30
  text ".Print_Date" at 2898,-1064.84 h30
  text "GENERATED    :" at 3767.5,-1064.84 h30
  text ".plot_File_Name" at 5440.5,-1064.84 h30
  text "PLOT NAME =" at 6246,-1064.84 h30
M9 Title Sheet:
  drawing of 57 lines, arcs and shapes, not listed
  text "1" at 739.84,8036.5 h70
  text "2" at 3235.5,8036.5 h70
  text "3" at 5724.84,8036.5 h70
  text "4" at 8231.51,8036.5 h70
  text "5" at 10730.5,8036.5 h70
  text "6" at 13235.5,8036.5 h70
  text "A" at -416.5,6893.5 h70
  text "A" at 14383.5,6893.5 h70
  text "B" at -416.5,4513.5 h70
  text "B" at 14383.5,4513.5 h70
  text "C" at -416.5,2138.5 h70
  text "C" at 14383.5,2138.5 h70
  text "PROJECT TITLE:" at 11343.5,277.5 h45
  text ".PRJ_Title" at 11393.5,144.17 h70
  text "DESIGNED FOR:" at 11343.5,-23.5 h45
  text ".PRJ_Customer" at 11393.5,-163.5 h70
  text "D" at -416.5,-231.5 h70
  text "D" at 14383.5,-231.5 h70
  text "FILE NAME:" at 11343.5,-323.5 h45
  text ".PCB_File_Name_No_Path" at 11393.5,-443.5 h70
  text "Texas Instruments (TI) and/or its licensors do not warrant the accuracy or completeness of this specification" at 6374,-605.34 h45
  text "ENGINEER:" at 11343.5,-613.5 h45
  text "LAYOUT BY:" at 12848.5,-613.5 h45
  text "or any information contained therein. TI and/or its licensors do not warrant that this design will meet" at 6329.01,-718 h45
  text ".PRJ_Engineer" at 11393.5,-768.49 h70
  text ".PCB_Layout" at 12899,-768.49 h70
  text "the specifications, will be suitable for your application or fit for any particular purpose, or will operate in" at 6329.01,-830.67 h45
  text ".Layer_Name" at 577,-858.49 h30
  text "ALTIUM DESIGNER VERSION:" at 12848.5,-923.5 h45
  text "an implementation. TI and/or its licensors do not warrant that the design is production worthy. You should" at 6329.01,-943.33 h45
  text "completely validate and test your design implementation to confirm the system functionality for your application." at 6374,-1056 h45
  text ".print_Scale" at 11393.5,-1056.83 h70
  text ".Application_BuildNumber" at 12899,-1056.83 h70
  text "1" at 739.84,-1263.5 h70
  text "2" at 3235.5,-1263.5 h70
  text "3" at 5724.84,-1263.5 h70
  text "4" at 8231.51,-1263.5 h70
  text "5" at 10730.5,-1263.5 h70
  text "6" at 13235.5,-1263.5 h70
M10 Fab Notes:
  drawing of 189 lines, arcs and shapes, not listed
  text "DESIGN INFORMATION" at 12382.02,6356.17 h30
  text "MIN. TRACK WIDTH:" at 11737.46,6224.05 h30
  text "8" at 12833.7,6224.05 h30
  text "MIL" at 12988.46,6224.05 h30
  text "MIN. CLEARANCE:" at 11737.46,6099.92 h30
  text "0.2" at 12773.7,6099.93 h30
  text "mm" at 12988.46,6099.92 h30
  text "MIN. VIA PAD SIZE:" at 11737.46,5975.8 h30
  text "24" at 12803.71,5975.8 h30
  text "MIL" at 12988.46,5975.8 h30
  text "0.05mm (2MIL)" at 12432.46,5845.9 h30
  text "MINIMUM ANNULAR RING" at 11408.23,5837.67 h30
  text "EXTERNAL" at 13140.46,5837.67 h30
  text "PER" at 11608.23,5727.55 h30
  text "IPC-D-275 CLASS 2 LEVEL C" at 11828.23,5727.54 h30
  text "MIL, HOLES" at 13316.46,5627.07 h30
  text "+/-" at 12924,5618.48 h30
  text "+/-" at 13778,5618.48 h30
  text "REGISTRATION TOLERANCES:" at 11408.23,5617.42 h30
  text "METAL" at 12608,5617.42 h30
  text "5" at 13184.2,5617.42 h30
  text "3" at 14017.2,5617.42 h30
  text "MIL" at 14133.46,5617.42 h30
  text "HOLE SIZE TOLERANCE (UNLESS OTHERWISE SPECIFIED):" at 11408.23,5519.1 h30
  text "+/-" at 13778,5516.23 h30
  text "3" at 14017.2,5515.17 h30
  text "MIL" at 14133.46,5515.17 h30
  text "MATERIAL:" at 11333.46,5377.52 h30
  text "FR-4 High Tg" at 12319.9,5249 h30
  text "X" at 12175.46,5241.01 h30
  text "FR-408" at 11754.46,5236.49 h30
  text "OTHER" at 13242.46,5236.49 h30
  text "62 MIL (1.6mm) +/-10%" at 12074.56,5093.46 h30
  text "X" at 11954.46,5091.01 h30
  text "THICKNESS:" at 11408.23,5085.24 h30
  text "OTHER" at 13359.46,5085.24 h30
  text "TOLERANCE:" at 11408.23,4946.92 h30
  text "X" at 12256.46,4946.92 h30
  text "ANSI IPC-6012 TYPE 3 CLASS 2" at 12434.48,4946.92 h30
  text "OTHER +/-" at 12434.46,4802.73 h30
  text "BOW & TWIST:" at 11408.23,4657.54 h30
  text "X" at 12256.46,4657.54 h30
  text "ANSI IPC-6012 TYPE 3 CLASS 2" at 12434.48,4657.54 h30
  text "OTHER +/-" at 12434.46,4510.85 h30
  text "DRILLING:" at 11333.46,4380.23 h30
  text "NC_DRILL FILES" at 13094.46,4275.04 h30
  text "REFERENCE:" at 11408.23,4271.1 h30
  text "X" at 12065.46,4271.01 h30
  text "AS SHOWN" at 12243.46,4271.1 h30
  text "X" at 12966.46,4271.1 h30
  text "OTHER" at 13392.46,4128.85 h30
  text "PTH COPPER THICKNESS:" at 11407.91,4125.32 h30
  text "X" at 12547.14,4125.32 h30
  text "20-30 um" at 12675.14,4125.32 h30
  text "BOARD FINISH:" at 11333.46,3977.73 h30
  text "SILKSCREEN:" at 11488.68,3867.6 h30
  text "X" at 12446.46,3867.6 h30
  text "TOP" at 12563.46,3867.6 h30
  text "X" at 12956.46,3867.6 h30
  text "BOTTOM" at 13074.46,3867.6 h30
  text "SILKSCREEN COLOR:" at 11488.68,3712.41 h30
  text "X" at 12445.46,3712.41 h30
  text "WHITE" at 12563.46,3712.41 h30
  text "OTHER" at 13074.46,3712.41 h30
  text "X" at 12576.46,3568.96 h30
  text "GREEN" at 12694.46,3568.96 h30
  text "OTHER" at 13312.46,3568.96 h30
  text "SOLDER RESIST COLOR:" at 11488.68,3562.1 h30
  text "X" at 12576.46,3414.71 h30
  text "MATTE" at 12694.46,3414.71 h30
  text "SEMI-GLOSS" at 13312,3414.07 h30
  text "IMMERSION GOLD (ENIG)" at 12394.46,3241.94 h30
  text "ENEPIG" at 13732,3234.72 h30
  text "SURFACE FINISH:" at 11333.46,3233.72 h30
  text "X" at 12216.46,3233.72 h30
  text "IMM. TIN/SILVER OR EQUIV" at 11663,3096.4 h30
  text "OTHER" at 13094.46,3092.47 h30
  text "ARRAY/PANEL:" at 11333.46,2937.09 h30
  text "CUT AND TRIM PER M1 BOARD OUTLINE" at 12394.46,2928.87 h30
  text "N.C. ROUTE" at 12394.46,2792.9 h30
  text "X" at 13082.46,2792.9 h30
  text "V. SCORE" at 13260.46,2792.9 h30
  text "CERTIFICATION:" at 11333.46,2663.77 h30
  text "MATERIALS AND WORKMANSHIP FOR ALL PCBS" at 12058.46,2663.77 h30
  text "TO MEET OR EXCEED THE REQUIREMENTS OF:" at 12058.46,2569.71 h30
  text "X" at 11695.97,2441.08 h30
  text "ANSI IPC-A-600F CLASS ->" at 11823.96,2441.08 h30
  text "X" at 13471.97,2441.08 h30
  text "2" at 13581.96,2441.08 h30
  text "1" at 13266.96,2439.58 h30
  text "3" at 13935.96,2439.58 h30
  text "X" at 12507.97,2293.39 h30
  text "RoHS" at 12635.96,2293.39 h30
  text "OTHER" at 13280.36,2293.39 h30
  text "PER ORDER" at 13677.42,2293.39 h30
  text "ALL BOARDS MUST MEET OR EXCEED UL94-V0 REQUIREMENTS." at 11361,2139.57 h30
  text "PCB MUST BEAR THE UL94V-0 UL REGISTERED MATERIAL ID NUMBER" at 11361,2023.5 h30
  text "ADDITIONAL REQUIREMENTS:" at 11333.46,1854.08 h30
  text "MICROSECTION:" at 11408.23,1746.95 h30
  text "YES" at 12313.96,1746.95 h30
  text "REQUIRED" at 13175.46,1602.62 h30
  text "BARE BOARD ELEC. TEST:" at 11408.23,1599.76 h30
  text "NONE" at 12713.96,1599.76 h30
  text "X" at 13057.46,1599.76 h30
  text "PER ORDER" at 13767.46,1599.76 h30
  text "XX MIL VIAS REQUIRE NON-CONDUCTIVE FILL AND PLANARIZE" at 11576.38,1394.82 h59
  text "XX MIL VIAS REQUIRE CONDUCTIVE FILL AND PLANARIZE" at 11584.38,1290.84 h30
  text "OUTER XX MIL TRACES REQUIRE 50 OHM SINGLE-ENDED IMPEDANCE" at 11583.39,1127.46 h58
  text "LAYER 2 & 3 (INNER LAYERS) XX MIL WIDE, XX MIL SPACE / TRACES REQUIRE 100 OHM DIFFERENTIAL IMPEDANCE" at 11575.39,891.74 h30
  text ".Layer_Name" at 577,-858.49 h30
M11 Gerber Information:
  lines w10: -292,-930.17 6308,-930.17 ; -292,-726.83 6310,-726.83 ; -292,-523.5 -292,-1133.5 3713,-1133.5 6310,-1133.5 6310,-523.5 -291.5,-523.5 -291.5,-1133.5 1284,-1133.5 ; 2173,-1133.5 2173,-523.5 ; 3440,-726.83 3440,-523.5 ; 4280,-726.83 4280,-523.5 ; 4902,-1140 4902,-937.17
  text "ALL ARTWORK VIEWED FROM TOP SIDE" at -228.5,-655.67 h30
  text "BOARD #:" at 2248,-655.67 h30
  text ".PRJ_Number" at 2793.5,-655.67 h30
  text "REV:" at 3638,-655.67 h30
  text ".PCB_Rev" at 3929.5,-655.67 h30
  text "SVN REV:" at 4476,-655.67 h30
  text ".VersionControl_RevNumber" at 4982,-655.67 h30
  text "LAYER NAME =" at -228.5,-858.49 h30
  text "TID #:" at 2248,-859 h30
  text ".TID" at 2793.5,-859 h30
  text "PLOT NAME =" at -228.5,-1064.34 h30
  text ".plot_File_Name" at 577,-1064.34 h30
  text "GENERATED    :" at 2250,-1064.34 h30
  text ".Print_Date" at 3119.5,-1064.34 h30
  text ".Print_Time" at 3848.5,-1064.34 h30
  text "TEXAS INSTRUMENTS" at 5113,-1064.34 h30
M12 Stackup:
  drawing of 295 lines, arcs and shapes, not listed
  text "Layer" at 9791.59,7919.94 h30
  text "Name" at 10006.55,7919.94 h30
  text "Material" at 10481.42,7919.94 h30
  text "Thickness" at 10921.31,7919.94 h30
  text "Constant" at 11256.22,7919.94 h30
  text "Board Layer Stack" at 11551.15,7919.94 h30
  text "Top Overlay" at 10006.55,7859.94 h30
  text "Top Solder" at 10006.55,7799.94 h30
  text "Solder Resist" at 10481.42,7799.94 h30
  text "0.40mil" at 10921.31,7799.94 h30
  text "3.5" at 11256.22,7799.94 h30
  text "1" at 9791.59,7739.94 h30
  text "Top Layer" at 10006.55,7739.94 h30
  text "1.40mil" at 10921.31,7739.94 h30
  text "Dielectric 1" at 10006.55,7679.94 h30
  text "PP-006" at 10481.42,7679.94 h30
  text "2.80mil" at 10921.31,7679.94 h30
  text "4.1" at 11256.22,7679.94 h30
  text "2" at 9791.59,7619.94 h30
  text "GND" at 10006.55,7619.94 h30
  text "CF-004" at 10481.42,7619.94 h30
  text "1.38mil" at 10921.31,7619.94 h30
  text "Dielectric1" at 10006.55,7559.94 h30
  text "FR-4" at 10481.42,7559.94 h30
  text "59.20mil" at 10921.31,7559.94 h30
  text "4.8" at 11256.22,7559.94 h30
  text "3" at 9791.59,7499.94 h30
  text "Signal" at 10006.55,7499.94 h30
  text "CF-004" at 10481.42,7499.94 h30
  text "1.38mil" at 10921.31,7499.94 h30
  text "Dielectric 2" at 10006.55,7439.94 h30
  text "PP-006" at 10481.42,7439.94 h30
  text "2.80mil" at 10921.31,7439.94 h30
  text "4.1" at 11256.22,7439.94 h30
  text "4" at 9791.59,7379.94 h30
  text "Bottom Layer" at 10006.55,7379.94 h30
  text "1.40mil" at 10921.31,7379.94 h30
  text "Bottom Solder" at 10006.55,7319.94 h30
  text "Solder Resist" at 10481.42,7319.94 h30
  text "0.40mil" at 10921.31,7319.94 h30
  text "3.5" at 11256.22,7319.94 h30
  text "Bottom Overlay" at 10006.55,7259.94 h30
  text ".Layer_Name" at 577,-858.49 h30
M13 Component Bodies Top:
  text ".Layer_Name" at 577,-858.49 h30
M14 Component Bodies Bottom:
  text ".Layer_Name" at 577,-858.49 h30
M15 Courtyards Top:
  text ".Layer_Name" at 577,-858.49 h30
M16 Courtyards Bottom:
  text ".Layer_Name" at 577,-858.49 h30
Drill Drawing:
  lines w10: 5312.57,3272 5340.14,3272 5326.35,3244.42 5312.57,3272 ; 5312.57,3306.47 5340.14,3306.47 5340.14,3334.05 5312.57,3334.05 5312.57,3306.47 ; 5312.57,3375.41 5319.46,3375.41 5326.35,3368.52 5333.25,3375.41 5340.14,3375.41 5333.25,3382.31 5340.14,3389.2 5333.25,3389.2 5326.35,3396.1 5319.46,3389.2 5312.57,3389.2 5319.46,3382.31 5312.57,3375.41
  lines w12: 5286,3225.81 6900.62,3225.81 ; 5286,3411.95 6900.62,3411.95 ; 5454.83,3163.76 5454.83,3474 ; 5620.76,3163.76 5620.76,3474 ; 5938.98,3163.76 5938.98,3474 ; 6068.48,3163.76 6068.48,3474 ; 6255.99,3163.76 6255.99,3474 ; 6617.51,3163.76 6617.51,3474 ; 5286,3163.76 6900.62,3163.76 6900.62,3474 5286,3474 5286,3163.76
  text "Symbol" at 5323.23,3430.57 h36
  text "Quantity" at 5473.44,3430.57 h36
  text "Finished Hole Size" at 5639.38,3430.57 h36
  text "Plated" at 5957.59,3430.57 h36
  text "Hole Type" at 6087.1,3430.57 h36
  text "Drill Layer Pair" at 6274.61,3430.57 h36
  text "Hole Tolerance" at 6636.12,3430.57 h36
  text "30" at 5473.44,3368.52 h30
  text "11.81mil (0.300mm)" at 5639.38,3368.52 h30
  text "PTH" at 5957.59,3368.52 h30
  text "Round" at 6087.1,3368.52 h30
  text "Top Layer - Bottom Layer" at 6274.61,3368.52 h30
  text "8" at 5473.44,3306.47 h30
  text "39.37mil (1.000mm)" at 5639.38,3306.47 h30
  text "PTH" at 5957.59,3306.47 h30
  text "Round" at 6087.1,3306.47 h30
  text "Top Layer - Bottom Layer" at 6274.61,3306.47 h30
  text "6" at 5473.44,3244.42 h30
  text "40.16mil (1.020mm)" at 5639.38,3244.42 h30
  text "PTH" at 5957.59,3244.42 h30
  text "Round" at 6087.1,3244.42 h30
  text "Top Layer - Bottom Layer" at 6274.61,3244.42 h30
  text "44 Total" at 5473.44,3182.37 h30
  text ".Layer_Name" at 577,-858.49 h30
M17 Embedded Cavity:
  text ".Layer_Name" at 577,-858.49 h30
M18 Embedded Assembly:
  text ".Layer_Name" at 577,-858.49 h30
M19 Embedded Keepout:
  text ".Layer_Name" at 577,-858.49 h30

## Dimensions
0,-400 to 1000,-400 on M2 Board Dimensions
0,0 to 0,1328.74 on M2 Board Dimensions
0,0 to 1255,0 on M2 Board Dimensions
